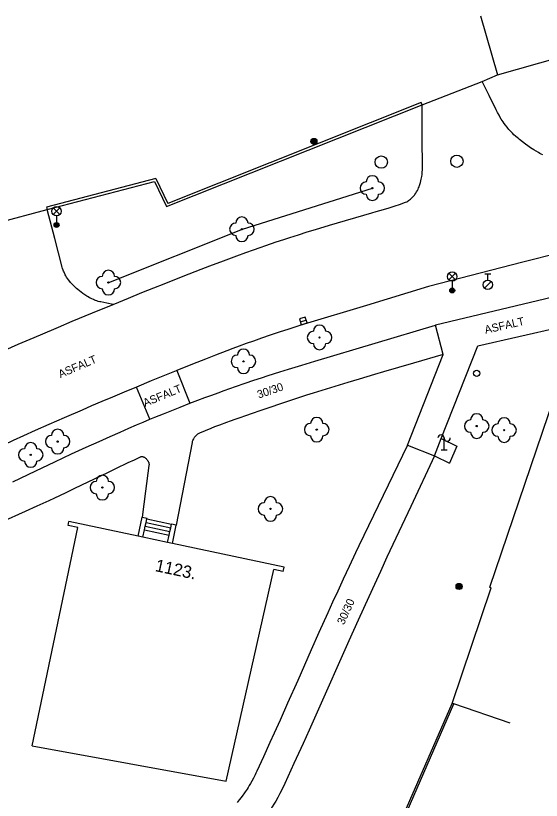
# Model space of a CAD drawing. Extents: x -538441 to -536770, y -1181008 to -1179809.
# Drawn here: x -538197.8 to -538155.1, y -1180684 to -1180620.3 of the extents above; entities that cross this region are included whole.
import ezdxf

# ---------------------------------------------------------------- set-up
doc = ezdxf.new("R2010")
doc.units = 0
for name, color, linetype in [('Vrstva 10', 7, 'Continuous'), ('Vrstva 11', 7, 'Continuous'), ('Vrstva 21', 7, 'Continuous'), ('Vrstva 22', 7, 'Continuous'), ('Vrstva 24', 7, 'Continuous'), ('Vrstva 25', 7, 'Continuous'), ('Vrstva 27', 7, 'Continuous'), ('Vrstva 28', 7, 'Continuous'), ('Vrstva 33', 7, 'Continuous'), ('Vrstva 40', 7, 'Continuous'), ('Vrstva 47', 7, 'Continuous'), ('Vrstva 5', 7, 'Continuous'), ('Vrstva 7', 7, 'Continuous'), ('Vrstva 8', 7, 'Continuous')]:
    doc.layers.add(name, color=color, linetype=linetype)

msp = doc.modelspace()

# ---------------------------------------------------------------- linework, layer by layer
at = {"layer": 'Vrstva 10'}
for p, q in [((-538148.87, -1180638.34), (-538156.55, -1180640.32)), ((-538156.55, -1180640.32), (-538164.23, -1180642.3)), ((-538164.23, -1180642.3), (-538169.275, -1180643.83)), ((-538189.86, -1180643.74), (-538188.608, -1180643.229)), ((-538169.275, -1180643.83), (-538174.32, -1180645.36)), ((-538192.376, -1180652.328), (-538193.819, -1180652.953))]:
    msp.add_line(p, q, dxfattribs=at)
for points in [[(-538158.723, -1180627.938), (-538159.292, -1180626.784), (-538159.86, -1180625.63)], [(-538165.768, -1180635.259), (-538165.7, -1180635.208), (-538165.637, -1180635.154), (-538165.577, -1180635.1), (-538165.522, -1180635.045), (-538165.47, -1180634.989), (-538165.422, -1180634.933), (-538165.377, -1180634.877), (-538165.335, -1180634.821), (-538165.257, -1180634.708), (-538165.189, -1180634.597), (-538165.13, -1180634.49), (-538165.078, -1180634.386), (-538165.033, -1180634.286), (-538164.994, -1180634.191), (-538164.96, -1180634.1), (-538164.929, -1180634.014), (-538164.879, -1180633.851), (-538164.84, -1180633.706), (-538164.811, -1180633.578), (-538164.789, -1180633.466), (-538164.772, -1180633.368), (-538164.748, -1180633.198), (-538164.735, -1180633.071), (-538164.728, -1180632.976), (-538164.722, -1180632.837), (-538164.72, -1180632.7), (-538164.735, -1180630.12), (-538164.75, -1180627.54)], [(-538157.513, -1180629.735), (-538157.609, -1180629.631), (-538157.696, -1180629.533), (-538157.774, -1180629.441), (-538157.846, -1180629.353), (-538157.974, -1180629.188), (-538158.081, -1180629.04), (-538158.171, -1180628.91), (-538158.246, -1180628.794), (-538158.311, -1180628.692), (-538158.419, -1180628.509), (-538158.498, -1180628.37), (-538158.612, -1180628.157), (-538158.723, -1180627.938)], [(-538154.948, -1180631.597), (-538155.069, -1180631.536), (-538155.181, -1180631.477), (-538155.287, -1180631.419), (-538155.484, -1180631.306), (-538155.656, -1180631.201), (-538155.806, -1180631.106), (-538155.936, -1180631.019), (-538156.164, -1180630.862), (-538156.334, -1180630.739), (-538156.588, -1180630.548), (-538156.84, -1180630.35), (-538156.925, -1180630.281), (-538157.005, -1180630.214), (-538157.154, -1180630.084), (-538157.287, -1180629.961), (-538157.406, -1180629.844), (-538157.513, -1180629.735)], [(-538168.486, -1180636.211), (-538167.884, -1180636.04), (-538167.434, -1180635.908), (-538167.097, -1180635.804), (-538166.845, -1180635.722), (-538166.656, -1180635.657), (-538166.514, -1180635.606), (-538166.302, -1180635.525), (-538166.09, -1180635.44), (-538166.001, -1180635.4), (-538165.918, -1180635.356), (-538165.84, -1180635.309), (-538165.768, -1180635.259)], [(-538172.274, -1180637.321), (-538168.83, -1180636.311), (-538168.486, -1180636.211)], [(-538178.459, -1180639.312), (-538177.914, -1180639.121), (-538177.437, -1180638.956), (-538176.6, -1180638.673), (-538175.97, -1180638.465), (-538175.498, -1180638.311), (-538174.787, -1180638.085), (-538174.075, -1180637.863), (-538173.421, -1180637.664), (-538172.274, -1180637.321)], [(-538179.79, -1180639.79), (-538179.081, -1180639.533), (-538178.459, -1180639.312)], [(-538188.608, -1180643.229), (-538187.511, -1180642.784), (-538186.551, -1180642.397), (-538185.71, -1180642.061), (-538184.973, -1180641.769), (-538183.682, -1180641.263), (-538182.712, -1180640.887), (-538181.984, -1180640.609), (-538180.888, -1180640.196), (-538179.79, -1180639.79)], [(-538198.65, -1180647.463), (-538197.557, -1180646.984), (-538196.599, -1180646.568), (-538195.76, -1180646.207), (-538194.289, -1180645.581), (-538193.184, -1180645.116), (-538191.524, -1180644.425), (-538189.86, -1180643.74)], [(-538174.32, -1180645.36), (-538174.755, -1180645.493), (-538175.176, -1180645.625), (-538175.583, -1180645.754), (-538176.369, -1180646.01), (-538177.104, -1180646.257), (-538177.792, -1180646.493), (-538178.435, -1180646.719), (-538179.037, -1180646.934), (-538179.6, -1180647.139), (-538180.127, -1180647.334), (-538180.62, -1180647.519), (-538181.543, -1180647.87), (-538182.349, -1180648.183), (-538183.053, -1180648.459), (-538183.669, -1180648.704)], [(-538183.669, -1180648.704), (-538184.686, -1180649.113), (-538184.744, -1180649.137), (-538185.549, -1180649.464), (-538186.755, -1180649.96), (-538187.96, -1180650.46), (-538188.963, -1180650.879), (-538189.902, -1180651.274), (-538190.782, -1180651.646), (-538191.605, -1180651.997), (-538192.376, -1180652.328)], [(-538193.819, -1180652.953), (-538195.079, -1180653.506), (-538196.179, -1180653.994), (-538197.14, -1180654.425), (-538197.98, -1180654.805), (-538198.713, -1180655.14), (-538199.995, -1180655.731), (-538200.954, -1180656.18), (-538201.672, -1180656.518), (-538202.747, -1180657.031)]]:
    msp.add_lwpolyline(points, dxfattribs=at)
at = {"layer": 'Vrstva 11'}
for p, q in [((-538194.6, -1180638.38), (-538195.21, -1180636.04)), ((-538146.74, -1180641.37), (-538163.67, -1180645.44)), ((-538160.23, -1180647.12), (-538145.61, -1180643.78)), ((-538168.565, -1180646.895), (-538163.67, -1180645.44)), ((-538163.03, -1180647.82), (-538163.67, -1180645.44)), ((-538173.46, -1180648.35), (-538168.565, -1180646.895)), ((-538163.2, -1180654.65), (-538160.23, -1180647.12)), ((-538165.932, -1180655.178), (-538163.03, -1180647.82)), ((-538184.686, -1180649.113), (-538183.61, -1180651.77)), ((-538177.259, -1180649.529), (-538176.312, -1180649.226)), ((-538186.868, -1180653.077), (-538187.96, -1180650.46)), ((-538163.748, -1180656.04), (-538163.2, -1180654.65)), ((-538163.2, -1180654.65), (-538161.93, -1180655.26)), ((-538165.932, -1180655.178), (-538163.748, -1180656.04)), ((-538161.93, -1180655.26), (-538162.52, -1180656.63)), ((-538163.748, -1180656.04), (-538162.52, -1180656.63)), ((-538197.992, -1180658.15), (-538196.13, -1180657.26)), ((-538187.116, -1180661.173), (-538185.11, -1180661.6)), ((-538187.24, -1180661.759), (-538185.234, -1180662.186)), ((-538187.178, -1180661.466), (-538185.172, -1180661.893)), ((-538187.303, -1180662.053), (-538185.297, -1180662.48)), ((-538170.688, -1180671.062), (-538173.28, -1180676.87))]:
    msp.add_line(p, q, dxfattribs=at)
for points in [[(-538189.86, -1180643.74), (-538190.356, -1180643.645), (-538190.851, -1180643.55), (-538190.926, -1180643.534), (-538191.066, -1180643.5), (-538191.186, -1180643.463), (-538191.29, -1180643.427), (-538191.379, -1180643.393), (-538191.457, -1180643.36), (-538191.592, -1180643.297), (-538191.692, -1180643.246), (-538191.767, -1180643.205), (-538191.879, -1180643.14), (-538191.99, -1180643.07), (-538192.16, -1180642.958), (-538192.316, -1180642.848), (-538192.461, -1180642.742), (-538192.593, -1180642.64), (-538192.715, -1180642.541), (-538192.826, -1180642.447), (-538192.927, -1180642.355), (-538193.02, -1180642.268), (-538193.105, -1180642.184), (-538193.182, -1180642.104), (-538193.252, -1180642.028), (-538193.316, -1180641.955), (-538193.374, -1180641.886), (-538193.477, -1180641.754), (-538193.563, -1180641.635), (-538193.633, -1180641.528), (-538193.691, -1180641.433), (-538193.739, -1180641.349), (-538193.778, -1180641.274), (-538193.842, -1180641.14), (-538193.885, -1180641.038), (-538193.915, -1180640.96), (-538193.955, -1180640.841), (-538193.99, -1180640.72), (-538194.6, -1180638.38)], [(-538163.03, -1180647.82), (-538165.459, -1180648.528), (-538167.888, -1180649.235), (-538168.604, -1180649.445), (-538169.855, -1180649.817), (-538170.792, -1180650.099), (-538172.197, -1180650.528)], [(-538176.312, -1180649.226), (-538175.601, -1180649.002), (-538174.531, -1180648.672), (-538173.46, -1180648.35)], [(-538185.762, -1180652.621), (-538185.226, -1180652.405), (-538184.419, -1180652.084), (-538183.61, -1180651.77), (-538182.983, -1180651.532), (-538182.395, -1180651.311), (-538181.842, -1180651.108), (-538181.323, -1180650.919), (-538180.836, -1180650.745), (-538179.921, -1180650.423), (-538179.119, -1180650.147), (-538178.415, -1180649.91), (-538177.799, -1180649.706), (-538177.259, -1180649.529)], [(-538172.197, -1180650.528), (-538173.6, -1180650.96), (-538174.144, -1180651.131), (-538174.619, -1180651.284), (-538175.448, -1180651.559), (-538177.929, -1180652.399), (-538178.549, -1180652.607), (-538179.089, -1180652.79), (-538179.561, -1180652.953), (-538179.973, -1180653.097), (-538180.333, -1180653.225), (-538180.647, -1180653.34), (-538181.197, -1180653.545), (-538181.608, -1180653.703)], [(-538187.424, -1180653.31), (-538186.868, -1180653.077), (-538186.476, -1180652.914), (-538185.762, -1180652.621)], [(-538196.13, -1180657.26), (-538194.585, -1180656.529), (-538193.23, -1180655.895), (-538192.042, -1180655.348), (-538191, -1180654.874), (-538190.086, -1180654.465), (-538189.284, -1180654.111), (-538188.581, -1180653.805), (-538187.964, -1180653.54), (-538187.424, -1180653.31)], [(-538181.608, -1180653.703), (-538181.917, -1180653.825), (-538182.379, -1180654.014), (-538182.84, -1180654.21), (-538182.895, -1180654.236), (-538182.946, -1180654.264), (-538182.991, -1180654.294)], [(-538182.991, -1180654.294), (-538183.033, -1180654.324), (-538183.071, -1180654.354), (-538183.139, -1180654.415), (-538183.194, -1180654.473), (-538183.239, -1180654.527), (-538183.275, -1180654.577), (-538183.304, -1180654.622), (-538183.328, -1180654.662), (-538183.366, -1180654.734), (-538183.39, -1180654.789), (-538183.405, -1180654.832), (-538183.425, -1180654.895), (-538183.44, -1180654.96), (-538184.079, -1180658.322), (-538184.718, -1180661.683)], [(-538165.932, -1180655.178), (-538167.906, -1180659.269), (-538169.88, -1180663.36), (-538170.152, -1180663.926)], [(-538188.121, -1180656.363), (-538187.62, -1180656.13), (-538187.596, -1180656.12), (-538187.573, -1180656.113), (-538187.528, -1180656.106), (-538187.488, -1180656.106), (-538187.453, -1180656.11), (-538187.422, -1180656.116), (-538187.395, -1180656.125), (-538187.347, -1180656.145), (-538187.312, -1180656.163), (-538187.26, -1180656.198), (-538187.21, -1180656.24), (-538187.174, -1180656.274), (-538187.143, -1180656.307), (-538187.089, -1180656.368), (-538187.049, -1180656.422)], [(-538163.748, -1180656.04), (-538165.674, -1180660.165), (-538167.6, -1180664.29)], [(-538196.977, -1180660.553), (-538196.017, -1180660.119), (-538195.06, -1180659.68), (-538194.593, -1180659.463), (-538193.719, -1180659.051), (-538192.955, -1180658.686), (-538190.288, -1180657.397), (-538189.621, -1180657.076), (-538188.621, -1180656.599), (-538188.121, -1180656.363)], [(-538187.049, -1180656.422), (-538187.018, -1180656.471), (-538186.995, -1180656.514), (-538186.978, -1180656.552), (-538186.965, -1180656.585), (-538186.948, -1180656.645), (-538186.94, -1180656.69), (-538186.937, -1180656.725), (-538186.936, -1180656.777), (-538186.94, -1180656.83), (-538187.216, -1180658.924), (-538187.491, -1180661.017)], [(-538200.181, -1180661.996), (-538198.9, -1180661.417), (-538196.977, -1180660.553)], [(-538170.152, -1180663.926), (-538170.673, -1180665.026), (-538171.156, -1180666.059), (-538171.604, -1180667.03), (-538172.021, -1180667.942), (-538172.409, -1180668.798), (-538173.13, -1180670.406), (-538173.757, -1180671.815)], [(-538167.6, -1180664.29), (-538168.131, -1180665.433), (-538168.625, -1180666.506), (-538169.086, -1180667.513), (-538169.943, -1180669.405), (-538170.688, -1180671.062)], [(-538173.757, -1180671.815), (-538174.85, -1180674.283), (-538175.671, -1180676.134), (-538176.289, -1180677.521), (-538176.756, -1180678.561), (-538177.109, -1180679.339), (-538177.642, -1180680.506)], [(-538173.28, -1180676.87), (-538173.93, -1180678.322), (-538174.419, -1180679.41), (-538175.157, -1180681.041), (-538175.9, -1180682.67), (-538176.005, -1180682.894), (-538176.106, -1180683.103), (-538176.203, -1180683.297), (-538176.297, -1180683.478), (-538176.386, -1180683.646), (-538176.472, -1180683.803), (-538176.638, -1180684.094), (-538176.79, -1180684.346), (-538176.926, -1180684.564), (-538177.049, -1180684.753), (-538177.16, -1180684.916), (-538177.259, -1180685.058), (-538177.436, -1180685.304), (-538177.574, -1180685.486), (-538177.68, -1180685.621)], [(-538177.642, -1180680.506), (-538178.18, -1180681.67), (-538178.253, -1180681.824), (-538178.323, -1180681.967), (-538178.459, -1180682.232), (-538178.583, -1180682.461), (-538178.696, -1180682.659), (-538178.798, -1180682.831), (-538178.889, -1180682.98), (-538178.971, -1180683.11)], [(-538178.971, -1180683.11), (-538179.119, -1180683.334), (-538179.234, -1180683.5), (-538179.323, -1180683.624), (-538179.459, -1180683.808), (-538179.6, -1180683.99), (-538179.772, -1180684.204)]]:
    msp.add_lwpolyline(points, dxfattribs=at)
at = {"layer": 'Vrstva 21'}
for p, q in [((-538179.34, -1180637.64), (-538168.79, -1180634.3)), ((-538190.19, -1180641.97), (-538179.34, -1180637.64))]:
    msp.add_line(p, q, dxfattribs=at)
at = {"layer": 'Vrstva 22'}
for centre in [(-538168.79, -1180634.3), (-538179.39, -1180637.64), (-538190.24, -1180641.97), (-538173.08, -1180646.43), (-538179.26, -1180648.37), (-538160.31, -1180653.63), (-538173.31, -1180653.92), (-538158.08, -1180653.96), (-538194.36, -1180654.89), (-538196.55, -1180655.97), (-538190.73, -1180658.62), (-538177.07, -1180660.36)]:
    msp.add_circle(centre, 0.05, dxfattribs=at)
for centre, start, end in [((-538169.29, -1180634.3), 90, 270), ((-538168.79, -1180633.8), 0, 180), ((-538168.29, -1180634.3), 270, 90), ((-538168.79, -1180634.8), 180, 0), ((-538179.39, -1180637.14), 0, 180), ((-538179.89, -1180637.64), 90, 270), ((-538178.89, -1180637.64), 270, 90), ((-538179.39, -1180638.14), 180, 0), ((-538190.74, -1180641.97), 90, 270), ((-538190.24, -1180641.47), 0, 180), ((-538189.74, -1180641.97), 270, 90), ((-538190.24, -1180642.47), 180, 0), ((-538173.58, -1180646.43), 90, 270), ((-538173.08, -1180645.93), 0, 180), ((-538172.58, -1180646.43), 270, 90), ((-538173.08, -1180646.93), 180, 0), ((-538179.26, -1180647.87), 0, 180), ((-538179.76, -1180648.37), 90, 270), ((-538178.76, -1180648.37), 270, 90), ((-538179.26, -1180648.87), 180, 0), ((-538173.31, -1180653.42), 0, 180), ((-538160.31, -1180653.13), 0, 180), ((-538173.81, -1180653.92), 90, 270), ((-538172.81, -1180653.92), 270, 90), ((-538160.81, -1180653.63), 90, 270), ((-538159.81, -1180653.63), 270, 90), ((-538158.58, -1180653.96), 90, 270), ((-538158.08, -1180653.46), 0, 180), ((-538157.58, -1180653.96), 270, 90), ((-538194.36, -1180654.39), 0, 180), ((-538160.31, -1180654.13), 180, 0), ((-538194.86, -1180654.89), 90, 270), ((-538193.86, -1180654.89), 270, 90), ((-538173.31, -1180654.42), 180, 0), ((-538158.08, -1180654.46), 180, 0), ((-538197.05, -1180655.97), 90, 270), ((-538196.55, -1180655.47), 0, 180), ((-538196.05, -1180655.97), 270, 90), ((-538194.36, -1180655.39), 180, 0), ((-538196.55, -1180656.47), 180, 0), ((-538190.73, -1180658.12), 0, 180), ((-538191.23, -1180658.62), 90, 270), ((-538190.23, -1180658.62), 270, 90), ((-538190.73, -1180659.12), 180, 0), ((-538177.57, -1180660.36), 90, 270), ((-538177.07, -1180659.86), 0, 180), ((-538176.57, -1180660.36), 270, 90), ((-538177.07, -1180660.86), 180, 0)]:
    msp.add_arc(centre, 0.5, start, end, dxfattribs=at)
at = {"layer": 'Vrstva 24'}
for p, q in [((-538162.96, -1180655.592), (-538162.96, -1180654.592)), ((-538162.71, -1180655.592), (-538163.21, -1180655.592))]:
    msp.add_line(p, q, dxfattribs=at)
for centre, start, end in [((-538163.21, -1180654.592), 0, 180), ((-538162.71, -1180654.592), 180, 0)]:
    msp.add_arc(centre, 0.25, start, end, dxfattribs=at)
at = {"layer": 'Vrstva 25'}
for centre, radius in [((-538173.54, -1180630.51), 0.25), ((-538173.54, -1180630.51), 0.2), ((-538173.54, -1180630.51), 0.15), ((-538173.54, -1180630.51), 0.1), ((-538173.54, -1180630.51), 0.05), ((-538161.74, -1180666.66), 0.25), ((-538161.74, -1180666.66), 0.2), ((-538161.74, -1180666.66), 0.15), ((-538161.74, -1180666.66), 0.1), ((-538161.74, -1180666.66), 0.05)]:
    msp.add_circle(centre, radius, dxfattribs=at)
at = {"layer": 'Vrstva 27'}
msp.add_line((-538174.646, -1180645.159), (-538174.168, -1180645.013), dxfattribs=at)
msp.add_lwpolyline([(-538174.573, -1180645.398), (-538174.095, -1180645.252), (-538174.241, -1180644.774), (-538174.719, -1180644.92)], close=True, dxfattribs=at)
for centre in [(-538168.06, -1180632.18), (-538161.92, -1180632.12)]:
    msp.add_circle(centre, 0.5, dxfattribs=at)
at = {"layer": 'Vrstva 28'}
for p, q in [((-538159.66, -1180641.275), (-538159.16, -1180641.275)), ((-538159.41, -1180641.775), (-538159.41, -1180641.275)), ((-538159.668, -1180642.422), (-538159.138, -1180641.892))]:
    msp.add_line(p, q, dxfattribs=at)
for centre, radius in [((-538159.41, -1180642.15), 0.375), ((-538160.31, -1180649.34), 0.25)]:
    msp.add_circle(centre, radius, dxfattribs=at)
at = {"layer": 'Vrstva 33'}
for p, q in [((-538194.715, -1180636.44), (-538194.185, -1180635.91)), ((-538194.715, -1180635.91), (-538194.185, -1180636.44)), ((-538194.45, -1180636.55), (-538194.45, -1180637.3)), ((-538162.565, -1180641.75), (-538162.035, -1180641.22)), ((-538162.565, -1180641.22), (-538162.035, -1180641.75)), ((-538162.3, -1180641.86), (-538162.3, -1180642.61))]:
    msp.add_line(p, q, dxfattribs=at)
for centre, radius in [((-538194.45, -1180636.175), 0.375), ((-538194.45, -1180637.3), 0.2), ((-538194.45, -1180637.3), 0.145), ((-538194.45, -1180637.3), 0.0876), ((-538162.3, -1180641.485), 0.375), ((-538162.3, -1180642.61), 0.2), ((-538162.3, -1180642.61), 0.145), ((-538162.3, -1180642.61), 0.0876)]:
    msp.add_circle(centre, radius, dxfattribs=at)
at = {"layer": 'Vrstva 5'}
for p, q in [((-538159.997, -1180620.293), (-538158.62, -1180625.1)), ((-538158.62, -1180625.1), (-538144.111, -1180620.942)), ((-538153.39, -1180649.39), (-538159.277, -1180666.733)), ((-538193.513, -1180661.712), (-538193.44, -1180661.37)), ((-538192.73, -1180661.879), (-538193.513, -1180661.712)), ((-538187.82, -1180662.565), (-538193.44, -1180661.37)), ((-538196.42, -1180679.6), (-538192.73, -1180661.879)), ((-538187.429, -1180662.648), (-538187.82, -1180662.565)), ((-538185.424, -1180663.075), (-538187.429, -1180662.648)), ((-538185.032, -1180663.158), (-538185.424, -1180663.075)), ((-538175.95, -1180665.09), (-538185.032, -1180663.158)), ((-538180.68, -1180682.47), (-538176.805, -1180665.266)), ((-538176.023, -1180665.432), (-538176.805, -1180665.266)), ((-538176.023, -1180665.432), (-538175.95, -1180665.09)), ((-538162.316, -1180676.156), (-538159.134, -1180666.781)), ((-538159.134, -1180666.781), (-538159.277, -1180666.733)), ((-538162.174, -1180676.204), (-538162.316, -1180676.156)), ((-538157.581, -1180677.763), (-538162.174, -1180676.204)), ((-538196.42, -1180679.6), (-538180.68, -1180682.47))]:
    msp.add_line(p, q, dxfattribs=at)
at = {"layer": 'Vrstva 7'}
for p, q in [((-538164.824, -1180627.354), (-538185.42, -1180635.545)), ((-538186.391, -1180633.515), (-538195.261, -1180635.847)), ((-538186.5, -1180633.75), (-538185.52, -1180635.8)), ((-538186.391, -1180633.515), (-538185.42, -1180635.545)), ((-538171.51, -1180697.23), (-538162.316, -1180676.156)), ((-538171.371, -1180697.287), (-538162.174, -1180676.204))]:
    msp.add_line(p, q, dxfattribs=at)
for points in [[(-538185.52, -1180635.8), (-538164.75, -1180627.54), (-538164.824, -1180627.354)], [(-538195.261, -1180635.847), (-538195.21, -1180636.04), (-538186.5, -1180633.75)], [(-538187.82, -1180662.565), (-538187.491, -1180661.017), (-538187.1, -1180661.1)], [(-538187.429, -1180662.648), (-538187.303, -1180662.053), (-538187.24, -1180661.759), (-538187.178, -1180661.466), (-538187.116, -1180661.173), (-538187.1, -1180661.1)], [(-538185.424, -1180663.075), (-538185.297, -1180662.48), (-538185.234, -1180662.186), (-538185.172, -1180661.893), (-538185.11, -1180661.6)], [(-538185.032, -1180663.158), (-538184.718, -1180661.683), (-538185.11, -1180661.6)]]:
    msp.add_lwpolyline(points, dxfattribs=at)
at = {"layer": 'Vrstva 8'}
for p, q in [((-538159.86, -1180625.63), (-538158.62, -1180625.1)), ((-538164.75, -1180627.54), (-538159.86, -1180625.63)), ((-538201.46, -1180637.72), (-538195.21, -1180636.04))]:
    msp.add_line(p, q, dxfattribs=at)

# ---------------------------------------------------------------- texts
at = {"layer": 'Vrstva 40'}
for s, rotation, p in [('ASFALT', 12.86862, (-538159.59, -1180646.132)), ('ASFALT', 23.28262, (-538194.14, -1180649.739)), ('ASFALT', 22.42708, (-538187.26, -1180652.08)), ('30/30', 18.73523, (-538178.021, -1180651.397)), ('30/30', 65.64839, (-538171.102, -1180669.823))]:
    msp.add_text(s, height=0.65, rotation=rotation, dxfattribs=at).set_placement(p)
at = {"layer": 'Vrstva 47'}
msp.add_text('1123.', height=1, rotation=347.99252, dxfattribs=at).set_placement((-538186.493, -1180665.403))

doc.saveas('drawing.dxf')
